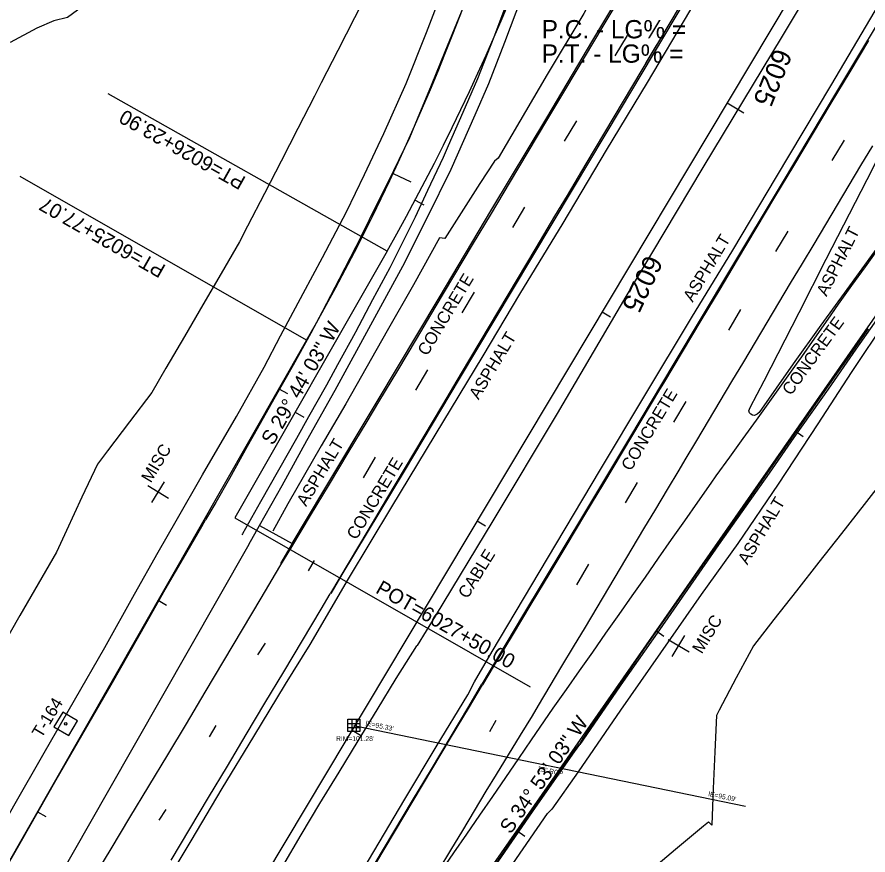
# Model space of a CAD drawing. Extents: x 2132221 to 2141942, y 535736 to 547298.
# Drawn here: x 2136948.6 to 2137298, y 538941.7 to 539285.8 of the extents above; entities that cross this region are included whole.
import ezdxf

# ---------------------------------------------------------------- set-up
doc = ezdxf.new("R2010")
doc.units = 0
for name, color, linetype in [('RD_EX_Conc', 7, 'Continuous'), ('RD_EX_Conc_txCode', 7, 'Continuous'), ('RD_EX_DR_Inlet', 7, 'Continuous'), ('RD_EX_DR_Inlet_txCode', 7, 'Continuous'), ('RD_EX_DR_Pipe', 7, 'Continuous'), ('RD_EX_DR_Pipe_txCode', 7, 'Continuous'), ('RD_EX_GuardRail', 7, 'Continuous'), ('RD_EX_GuardRail_txCode', 7, 'Continuous'), ('RD_EX_H2O', 7, 'Continuous'), ('RD_EX_Misc', 7, 'Continuous'), ('RD_EX_Misc_txCode', 7, 'Continuous'), ('RD_EX_Road', 7, 'Continuous'), ('RD_EX_Road_txCode', 7, 'Continuous'), ('RD_EX_VEG', 7, 'Continuous'), ('RD_HC_Cl', 7, 'Continuous'), ('RD_HC_Data', 7, 'Continuous'), ('RD_HC_Data_Tic', 7, 'Continuous'), ('RD_HC_Survey', 7, 'Continuous'), ('RD_HC_Survey_txCode', 7, 'Continuous'), ('RD_HC_TX_Sta50', 7, 'Continuous')]:
    doc.layers.add(name, color=color, linetype=linetype)

msp = doc.modelspace()

# ---------------------------------------------------------------- linework, layer by layer
at = {"layer": 'RD_EX_Conc'}
for points in [[(2137043.74, 539069.23), (2137048.13, 539076.97), (2137061.58, 539069.64), (2137074.6, 539091.41), (2137096.49, 539127.9), (2137121.9, 539170.45), (2137143.59, 539206.82), (2137166.07, 539244.36), (2137185, 539276.21), (2137210.45, 539318.75), (2137229.51, 539350.48), (2137242.23, 539372.03)], [(2137263.04, 539359.5), (2137240.58, 539321.84), (2137218.76, 539285.38), (2137196.3, 539247.74), (2137176.97, 539215.44), (2137151.95, 539173.6), (2137130.16, 539137.26), (2137107.61, 539099.35), (2137082.02, 539056.89), (2137077.38, 539049.09)], [(2137333.67, 539335.96), (2137310.86, 539297.96), (2137285.52, 539255.72), (2137262.8, 539217.71), (2137241.15, 539181.64), (2137218.32, 539143.58), (2137200.03, 539113.05), (2137181.55, 539082.16), (2137156.17, 539039.86), (2137139.5, 539011.87)], [(2137386.22, 539279.28), (2137375.65, 539265.67), (2137364.42, 539250.49), (2137352.58, 539233.98), (2137342.73, 539219.91), (2137331.08, 539203.52), (2137316.82, 539183.44), (2137303.12, 539163.77), (2137293.03, 539149.45), (2137281.61, 539133.04), (2137267.61, 539113.07), (2137257.39, 539098.52), (2137236.65, 539069.06), (2137212.4, 539034.24), (2137197.5, 539013.03), (2137179.75, 538987.14)], [(2137305.67, 539196.39), (2137289.35, 539173.96), (2137278.64, 539159.19), (2137267.29, 539143.37), (2137253.27, 539123.42), (2137252.5, 539122.73), (2137251.44, 539122.22), (2137250.52, 539122.34), (2137249.86, 539122.69), (2137249.3, 539123.27), (2137249.09, 539124.11), (2137249.68, 539125.49), (2137255.39, 539136.35), (2137269.77, 539164.45), (2137280.85, 539186.41), (2137297.62, 539219.08), (2137309.33, 539241.89)], [(2137043.74, 539069.23), (2137018.81, 539025.51), (2136986.13, 538968.22), (2136875.05, 538773.45), (2136825.81, 538687.13), (2136799.99, 538643.84), (2136781.97, 538653.73)], [(2137095.66, 538938.35), (2137103.33, 538951.23), (2137111, 538964.13), (2137118.71, 538977), (2137126.43, 538989.86), (2137134.16, 539002.71), (2137139.5, 539011.87)], [(2137143.23, 538934.82), (2137151.78, 538947.15), (2137160.31, 538959.49), (2137168.91, 538971.77), (2137177.54, 538984.04), (2137179.75, 538987.14)]]:
    msp.add_lwpolyline(points, dxfattribs=at)
at = {"layer": 'RD_EX_DR_Inlet'}
for p, q in [((2137084.37, 538995.74), (2137089.37, 538995.74)), ((2137086.07, 538997.44), (2137086.07, 538992.44)), ((2137087.77, 538997.44), (2137087.77, 538992.44)), ((2137084.37, 538994.04), (2137089.37, 538994.04))]:
    msp.add_line(p, q, dxfattribs=at)
msp.add_lwpolyline([(2137084.37, 538992.44), (2137084.37, 538997.44), (2137089.37, 538997.44), (2137089.37, 538992.44)], close=True, dxfattribs=at)
at = {"layer": 'RD_EX_DR_Pipe'}
msp.add_line((2137086.91, 538994.89), (2137247.7, 538961.76), dxfattribs=at)
at = {"layer": 'RD_EX_GuardRail'}
for points in [[(2137297.36, 539335.79), (2137262.72, 539277.83), (2137230.19, 539223.92), (2137198.56, 539171.04), (2137170.43, 539122.99), (2137143.89, 539078.9), (2137120.24, 539039.74), (2137112.85, 539027.78)], [(2137057.71, 538937.12), (2137065.32, 538950.05), (2137072.98, 538962.94), (2137080.8, 538975.74), (2137088.62, 538988.54), (2137096.44, 539001.34), (2137104.26, 539014.14), (2137112.76, 539027.64), (2137112.85, 539027.78)]]:
    msp.add_lwpolyline(points, dxfattribs=at)
at = {"layer": 'RD_EX_H2O'}
msp.add_lwpolyline([(2136937.08, 539329.41), (2136956.9, 539325.01), (2136966.82, 539319.9), (2136976.74, 539314.8), (2136985.96, 539311.64), (2136992.18, 539307.69), (2136992.58, 539303.51), (2136991.26, 539300.03), (2136985.6, 539294.77), (2136975.47, 539290.12), (2136969.24, 539285.53), (2136963.66, 539284.21), (2136956.68, 539281.22), (2136945.76, 539275.36)], dxfattribs=at)
at = {"layer": 'RD_EX_Misc'}
for p, q in [((2137194.21, 539269.77), (2137199.21, 539278.16)), ((2137173.4, 539234.72), (2137178.4, 539243.1)), ((2137283.36, 539226.83), (2137288.35, 539235.21)), ((2137152.14, 539199.3), (2137157.14, 539207.68)), ((2137260.2, 539189.45), (2137265.2, 539197.84)), ((2137131.4, 539164.34), (2137136.39, 539172.73)), ((2137240.83, 539157.23), (2137245.83, 539165.62)), ((2137112.34, 539132.59), (2137117.33, 539140.98)), ((2137218.3, 539119.47), (2137223.3, 539127.86)), ((2137090.79, 539096.64), (2137095.78, 539105.03)), ((2137010.81, 539088.12), (2137002.24, 539093.28)), ((2137003.94, 539086.41), (2137009.1, 539094.98)), ((2137198.44, 539086.3), (2137203.43, 539094.68)), ((2137068.33, 539058.34), (2137070.79, 539062.59)), ((2137178.39, 539052.71), (2137183.39, 539061.1)), ((2137224.52, 539024.96), (2137215.95, 539030.12)), ((2137217.66, 539023.25), (2137222.81, 539031.82)), ((2137047.48, 539023.93), (2137050.57, 539028.67)), ((2137027.64, 538990.23), (2137030.35, 538994.94)), ((2137142.72, 538992.44), (2137145.33, 538997.06)), ((2137006.93, 538955.99), (2137009.76, 538960.47))]:
    msp.add_line(p, q, dxfattribs=at)
for points in [[(2137135.61, 539299.29), (2137129.93, 539285.41), (2137124.25, 539271.53), (2137118.57, 539257.64), (2137112.89, 539243.76), (2137109.76, 539236.1), (2137103.14, 539222.64), (2137096.51, 539209.18), (2137089.89, 539195.72), (2137087.76, 539191.38), (2137080.81, 539178.08), (2137073.86, 539164.79), (2137069.25, 539155.97), (2137061.91, 539142.89), (2137054.57, 539129.81), (2137047.23, 539116.73), (2137043.1, 539109.37), (2137035.76, 539096.29), (2137030.26, 539086.49), (2137026.01, 539079.34)], [(2137152.33, 539298.79), (2137147.11, 539284.73), (2137144.42, 539277.48), (2137138.87, 539263.55), (2137137.6, 539260.34), (2137131.61, 539246.59), (2137125.61, 539232.84), (2137123.53, 539228.08), (2137117.16, 539214.5), (2137112.02, 539203.55), (2137105.29, 539190.15), (2137101.62, 539182.85), (2137094.59, 539169.59), (2137087.57, 539156.34), (2137087.43, 539156.1), (2137080.23, 539142.94), (2137075.66, 539134.6), (2137068.28, 539121.55), (2137063.32, 539112.78), (2137055.93, 539099.72), (2137048.54, 539086.67), (2137041.16, 539073.61), (2137040.89, 539073.13)], [(2137196.83, 539294.84), (2137189.14, 539281.96), (2137181.45, 539269.08), (2137173.75, 539256.21), (2137166.06, 539243.33), (2137158.37, 539230.45), (2137150.68, 539217.57), (2137143.22, 539205.08), (2137135.52, 539192.2), (2137127.83, 539179.33), (2137120.14, 539166.45), (2137112.45, 539153.57), (2137104.76, 539140.69), (2137097.06, 539127.82), (2137092.18, 539119.65), (2137084.45, 539106.79), (2137076.72, 539093.94), (2137068.99, 539081.09), (2137061.25, 539068.24), (2137056.36, 539060.11)], [(2137220.54, 539289.83), (2137212.86, 539276.95), (2137205.17, 539264.06), (2137197.49, 539251.18), (2137189.8, 539238.3), (2137182.12, 539225.42), (2137174.43, 539212.54), (2137169.31, 539203.95), (2137161.65, 539191.06), (2137153.98, 539178.16), (2137146.32, 539165.27), (2137138.65, 539152.38), (2137130.99, 539139.48), (2137123.32, 539126.59), (2137115.66, 539113.69), (2137107.99, 539100.8), (2137100.33, 539087.91), (2137092.67, 539075.01), (2137085, 539062.12), (2137077.34, 539049.22), (2137077.16, 539048.93)], [(2137298.19, 539276.12), (2137290.49, 539263.25), (2137282.79, 539250.38), (2137275.08, 539237.51), (2137267.38, 539224.64), (2137259.67, 539211.76), (2137251.97, 539198.89), (2137244.27, 539186.02), (2137237.13, 539174.09), (2137229.42, 539161.22), (2137221.72, 539148.35), (2137214.01, 539135.48), (2137212.46, 539132.87), (2137204.75, 539120), (2137197.05, 539107.13), (2137189.34, 539094.26), (2137181.64, 539081.39), (2137173.94, 539068.52), (2137167.36, 539057.54), (2137159.61, 539044.69), (2137151.87, 539031.85), (2137144.12, 539019.01), (2137139.66, 539011.62)], [(2137299.8, 539232.86), (2137294.99, 539224.8), (2137290.17, 539216.74), (2137285.36, 539208.68), (2137280.55, 539200.62), (2137275.73, 539192.56), (2137270.92, 539184.51), (2137266.1, 539176.43), (2137261.29, 539168.38), (2137256.47, 539160.32), (2137251.66, 539152.26), (2137246.85, 539144.2), (2137242.03, 539136.14), (2137237.22, 539128.08), (2137232.41, 539120.02), (2137227.59, 539111.96), (2137222.78, 539103.9), (2137220.32, 539099.79), (2137215.51, 539091.73), (2137210.69, 539083.67), (2137205.88, 539075.61), (2137201.07, 539067.55), (2137196.25, 539059.5), (2137191.44, 539051.44), (2137186.63, 539043.38), (2137181.81, 539035.32), (2137177, 539027.26), (2137172.19, 539019.2), (2137167.37, 539011.14), (2137162.56, 539003.08), (2137160.05, 538998.87), (2137155.14, 538990.87), (2137150.24, 538982.86), (2137145.34, 538974.85), (2137141.1, 538967.93), (2137136.27, 538959.88), (2137131.44, 538951.83), (2137126.61, 538943.78), (2137121.79, 538935.73)], [(2137124.59, 538937.81), (2137127.93, 538942.57), (2137133.26, 538950.32), (2137138.59, 538958.06), (2137143.91, 538965.81), (2137149.24, 538973.56), (2137154.57, 538981.3), (2137159.9, 538989.05), (2137165.23, 538996.8), (2137168.78, 539001.96), (2137174.18, 539009.65), (2137179.58, 539017.35), (2137184.98, 539025.05), (2137190.38, 539032.74), (2137195.78, 539040.44), (2137201.18, 539048.14), (2137206.58, 539055.84), (2137211.98, 539063.53), (2137217.38, 539071.23), (2137222.78, 539078.93), (2137228.18, 539086.62), (2137233.58, 539094.32), (2137235.73, 539097.39), (2137241.22, 539105.02), (2137246.7, 539112.66), (2137252.19, 539120.3), (2137257.67, 539127.93), (2137263.16, 539135.57), (2137268.64, 539143.21), (2137270.81, 539146.23), (2137276.2, 539153.94), (2137281.59, 539161.65), (2137285.95, 539167.9), (2137291.44, 539175.53), (2137296.93, 539183.17), (2137302.42, 539190.8)], [(2137298.09, 539157.76), (2137289.48, 539145.47), (2137286.74, 539141.56), (2137278.13, 539129.27), (2137269.53, 539116.99), (2137260.92, 539104.7), (2137252.32, 539092.41), (2137248.92, 539087.56), (2137240.31, 539075.27), (2137231.71, 539062.99), (2137223.1, 539050.7), (2137214.5, 539038.42), (2137205.89, 539026.13), (2137202.25, 539020.93), (2137193.79, 539008.53), (2137185.34, 538996.14), (2137180.88, 538989.6), (2137179.48, 538987.33)], [(2136942.36, 538933.52), (2136949.81, 538946.54), (2136957.28, 538959.55), (2136964.71, 538972.58), (2136972.19, 538985.58), (2136979.71, 538998.56), (2136987.17, 539011.57), (2136994.61, 539024.6), (2137001.98, 539037.66), (2137009.43, 539050.68), (2137016.95, 539063.66), (2137024.45, 539076.65), (2137026.01, 539079.34)], [(2137061.58, 539069.64), (2137056.72, 539061.46)], [(2137056.36, 539060.11), (2137048.7, 539047.21), (2137041.04, 539034.32), (2137033.38, 539021.42), (2137025.71, 539008.53), (2137018.04, 538995.64), (2137010.3, 538982.79), (2137002.56, 538969.94), (2136994.82, 538957.09), (2136987.08, 538944.24), (2136979.35, 538931.39)], [(2137011.88, 538939.64), (2137019.56, 538952.52), (2137027.25, 538965.4), (2137034.95, 538978.27), (2137042.66, 538991.14), (2137050.38, 539004), (2137058.08, 539016.87), (2137065.76, 539029.76), (2137073.43, 539042.65), (2137077.16, 539048.93)], [(2137095.87, 538938.22), (2137103.54, 538951.11), (2137111.21, 538964), (2137118.92, 538976.87), (2137126.64, 538989.73), (2137134.38, 539002.58), (2137139.66, 539011.62)], [(2137142.97, 538935.01), (2137151.52, 538947.33), (2137160.05, 538959.67), (2137168.65, 538971.96), (2137177.28, 538984.22), (2137179.48, 538987.33)]]:
    msp.add_lwpolyline(points, dxfattribs=at)
at = {"layer": 'RD_EX_Road'}
for points in [[(2137048.13, 539076.97), (2137057.39, 539093.44), (2137067.57, 539111.87), (2137079.22, 539132.53), (2137094.62, 539160.88), (2137106.97, 539183.5), (2137117.14, 539203.56), (2137126.87, 539223.28), (2137136.64, 539245.56), (2137142.29, 539258.43), (2137148.92, 539275.38), (2137155.88, 539294.04), (2137161, 539308.74), (2137165.87, 539324.26), (2137168.83, 539333.05), (2137173.16, 539346.96), (2137178.88, 539367.59), (2137184.45, 539388.35), (2137189.41, 539410.75)], [(2137006.53, 539066.01), (2137013.89, 539078.91), (2137024.77, 539097.78), (2137038.63, 539121.79), (2137050.02, 539142.02), (2137056.82, 539154.91), (2137066.02, 539172.3), (2137073.99, 539186.99), (2137083.8, 539205.71), (2137091.28, 539221.05), (2137099.16, 539237.88), (2137108.37, 539258.44), (2137116.77, 539279.44), (2137124.59, 539300.19), (2137133.06, 539323.8), (2137140.3, 539346.76), (2137147.25, 539369.82), (2137153.61, 539394.27), (2137157.16, 539408.42)], [(2137231.11, 539371.27), (2137209.1, 539334.87), (2137190.96, 539304.41), (2137187.5, 539298.93), (2137181.36, 539287.14), (2137166.25, 539262.11), (2137146.11, 539227.86), (2137144.58, 539226.64), (2137138.66, 539217.45), (2137124.26, 539194.84), (2137122.04, 539195.11), (2137111.32, 539175.78), (2137100.54, 539156.89), (2137083.66, 539126.93), (2137073.42, 539109.73), (2137059.72, 539085.91), (2137053.68, 539074.62)], [(2137068.88, 539028.2), (2137084.75, 539055.08), (2137102.46, 539084.72), (2137120.25, 539114.08), (2137139.97, 539146.71), (2137155, 539172.04), (2137172.78, 539201.18), (2137190.67, 539231.04), (2137207.43, 539258.89), (2137224.9, 539288.17), (2137243.07, 539319.08), (2137262.82, 539351.95)], [(2137136.47, 539012.76), (2137143.68, 539025.32), (2137166.46, 539063.47), (2137188.17, 539100.06), (2137206.31, 539130.4), (2137225.59, 539162.23), (2137242.51, 539190.02), (2137260.51, 539220.13), (2137282.76, 539257.55), (2137308.14, 539300.44), (2137324.83, 539328.87)], [(2137390.6, 539276.98), (2137381.06, 539264.66), (2137366.46, 539244.94), (2137351.69, 539226.13), (2137339.88, 539209.47), (2137328.84, 539193.7), (2137317.64, 539177.92), (2137305.73, 539161.76), (2137291.11, 539139.83), (2137277.39, 539118.75), (2137261.14, 539093.92), (2137244.5, 539069.57), (2137229.53, 539048.64), (2137216.9, 539030.62), (2137196.32, 539001.16), (2137178.95, 538975.86), (2137168.15, 538960.62)], [(2136770.79, 538659.14), (2136783.63, 538680.59), (2136796.16, 538702.23), (2136808.9, 538723.74), (2136821.39, 538745.87), (2136834.05, 538767.44), (2136846.42, 538789.18), (2136859.14, 538810.7), (2136872.07, 538832.1), (2136884.7, 538853.67), (2136897.03, 538875.43), (2136910.25, 538896.65), (2136922.71, 538918.33), (2136935.01, 538940.1), (2136947.29, 538961.89), (2136959.67, 538983.61), (2136972.2, 539005.25), (2136984.61, 539026.96), (2136996.87, 539048.76), (2137006.53, 539066.01)], [(2137007.23, 538926.11), (2137020.07, 538947.56), (2137032.88, 538969.03), (2137045.78, 538990.45), (2137058.77, 539011.81), (2137068.88, 539028.2)], [(2137082.37, 538921.67), (2137095.07, 538943.2), (2137107.85, 538964.69), (2137120.74, 538986.12), (2137133.63, 539007.53), (2137136.47, 539012.76)], [(2137152.13, 538938.16), (2137166.37, 538958.77), (2137168.15, 538960.62)]]:
    msp.add_lwpolyline(points, dxfattribs=at)
at = {"layer": 'RD_EX_VEG'}
for points in [[(2137094.05, 539298.73), (2137087.2, 539285.39), (2137080.34, 539272.04), (2137073.48, 539258.7), (2137070.71, 539253.31), (2137063.85, 539239.97), (2137056.99, 539226.63), (2137050.14, 539213.29), (2137043.28, 539199.94), (2137039.95, 539193.46), (2137032.39, 539180.5), (2137024.84, 539167.54), (2137017.29, 539154.58), (2137009.73, 539141.62), (2137003.87, 539131.56), (2136994.8, 539119.61), (2136985.73, 539107.66), (2136981.57, 539102.17)], [(2136981.57, 539102.17), (2136975.23, 539088.58), (2136968.89, 539074.98), (2136964.74, 539066.1), (2136957.26, 539053.1), (2136949.78, 539040.09), (2136942.29, 539027.09), (2136934.81, 539014.09), (2136927.33, 539001.09), (2136919.85, 538988.09), (2136917.15, 538983.4), (2136910.48, 538969.97), (2136903.8, 538956.54), (2136897.12, 538943.11), (2136890.44, 538929.68)], [(2137305.66, 539097.39), (2137296.4, 539085.59), (2137287.15, 539073.78), (2137277.89, 539061.98), (2137268.64, 539050.18), (2137259.38, 539038.37), (2137250.97, 539027.64), (2137243.91, 539014.4), (2137236.86, 539001.16), (2137235.74, 538999.06), (2137235.11, 538984.08), (2137234.47, 538969.09), (2137233.84, 538954.1), (2137233.84, 538953.94), (2137232.55, 538955.42)], [(2137207.48, 538934.45), (2137218.98, 538944.07), (2137230.49, 538953.7), (2137232.55, 538955.42)]]:
    msp.add_lwpolyline(points, dxfattribs=at)
at = {"layer": 'RD_HC_Cl'}
for p, q in [((2139719.79, 543396.28), (2136851.48, 538600.7)), ((2137342.26, 539222.2), (2136996.48, 538726.24)), ((2137100.55, 539189.59), (2137038.01, 539080.1)), ((2137067.5, 539153.07), (2136783.32, 538655.35))]:
    msp.add_line(p, q, dxfattribs=at)
for centre, radius, start, end in [((2136251.89, 539668.21), 974.32, 330.57825, 1.35319), ((2136237.58, 539626.93), 955.67, 330.27494, 1.67918)]:
    msp.add_arc(centre, radius, start, end, dxfattribs=at)
at = {"layer": 'RD_HC_Data'}
for p, q in [((2137100.55, 539189.59), (2136985.96, 539254.22)), ((2137067.5, 539153.07), (2136949.85, 539220.24)), ((2137067.5, 539153.07), (2136949.85, 539220.24)), ((2137038.01, 539080.1), (2137159.35, 539010.79))]:
    msp.add_line(p, q, dxfattribs=at)
at = {"layer": 'RD_HC_Data_Tic'}
for p, q in [((2137240.14, 539250.5), (2137247.01, 539246.4)), ((2137102.97, 539221.46), (2137110.22, 539218.06)), ((2137102.97, 539221.46), (2137110.22, 539218.06)), ((2137112.03, 539210.55), (2137115.57, 539208.67)), ((2137188.81, 539164.68), (2137192.24, 539162.63)), ((2137056.13, 539133.15), (2137059.6, 539131.17)), ((2137056.13, 539133.15), (2137059.6, 539131.17)), ((2137062.81, 539123.51), (2137066.28, 539121.53)), ((2137268.14, 539115.88), (2137271.42, 539113.6)), ((2137137.48, 539078.86), (2137140.91, 539076.81)), ((2137006.54, 539046.31), (2137010.02, 539044.32)), ((2137006.54, 539046.31), (2137010.02, 539044.32)), ((2137210.95, 539033.85), (2137214.23, 539031.57)), ((2137086.15, 538993.04), (2137089.58, 538990.99)), ((2136956.96, 538959.47), (2136960.43, 538957.48)), ((2136956.96, 538959.47), (2136960.43, 538957.48)), ((2137153.76, 538951.82), (2137157.04, 538949.53))]:
    msp.add_line(p, q, dxfattribs=at)
at = {"layer": 'RD_HC_Survey'}
msp.add_lwpolyline([(2136967.37, 539000.43), (2136963.73, 538994.37), (2136969.79, 538990.73), (2136973.43, 538996.79)], close=True, dxfattribs=at)
msp.add_circle((2136968.58, 538995.58), 0.5, dxfattribs=at)

# ---------------------------------------------------------------- texts
at = {"layer": 'RD_EX_Conc_txCode'}
for rotation, p in [(58.9562, (2137116.99, 539146.31)), (53.8961, (2137266.36, 539130.07)), (58.9562, (2137200.61, 539099.04)), (58.9562, (2137087.88, 539070.78))]:
    msp.add_text('CONCRETE', height=5, rotation=rotation, dxfattribs=at).set_placement(p)
at = {"layer": 'RD_EX_DR_Inlet_txCode'}
for s, p in [("IE=95.33'", (2137091.51, 538994.96)), ("IE=95.09'", (2137232.25, 538965.96))]:
    msp.add_text(s, height=2, rotation=348.358, dxfattribs=at).set_placement(p)
msp.add_text("RIM=101.28'", height=2, dxfattribs=at).set_placement((2137079.58, 538988.52))
at = {"layer": 'RD_EX_DR_Pipe_txCode'}
msp.add_text('15" RCP', height=2, rotation=348.358, dxfattribs=at).set_placement((2137162.16, 538976.32))
at = {"layer": 'RD_EX_GuardRail_txCode'}
msp.add_text('CABLE', height=5, rotation=58.014, dxfattribs=at).set_placement((2137133.54, 539046.62))
at = {"layer": 'RD_EX_Misc_txCode'}
for p in [(2137002.57, 539092.6), (2137228.81, 539022.42)]:
    msp.add_text(' MISC', height=5, rotation=58.9562, dxfattribs=at).set_placement(p)
at = {"layer": 'RD_EX_Road_txCode'}
for rotation, p in [(63.195, (2137281.02, 539170.75)), (58.9562, (2137226.01, 539168.41)), (58.9562, (2137138.1, 539128.38)), (58.9562, (2137067.28, 539084.51)), (58.9562, (2137248.47, 539060.59))]:
    msp.add_text('ASPHALT', height=5, rotation=rotation, dxfattribs=at).set_placement(p)
at = {"layer": 'RD_HC_Data'}
for s, p in [('P.C. - LG% = ', (2137164, 539277)), ('P.T. - LG% = ', (2137164, 539267))]:
    msp.add_text(s, height=7.5, dxfattribs=at).set_placement(p)
for s, rotation, p in [('PT=6026+23.90', 150.5783, (2137042.95, 539219.78)), ('PT=6025+77.07', 150.2749, (2137010.06, 539183.56)), ('PT=6025+77.07', 150.2749, (2137010.06, 539183.56)), ('S 29%%d 44\' 03" W', 60.2657, (2137053.71, 539109.6)), ('POT=6027+50.00', 330.2657, (2137095.44, 539049.59)), ('S 34%%d 53\' 03" W', 55.1157, (2137151.27, 538950))]:
    msp.add_text(s, height=6, rotation=rotation, dxfattribs=at).set_placement(p)
at = {"layer": 'RD_HC_Survey_txCode'}
msp.add_text('T-164', height=5, rotation=58.9562, dxfattribs=at).set_placement((2136958.66, 538989.4))
at = {"layer": 'RD_HC_TX_Sta50'}
for rotation, p in [(247.8643, (2137259.71, 539273.35)), (244.8953, (2137206.85, 539188.61)), (244.8953, (2137206.85, 539188.61))]:
    msp.add_text('6025', height=8, rotation=rotation, dxfattribs=at).set_placement(p)

doc.saveas('drawing.dxf')
